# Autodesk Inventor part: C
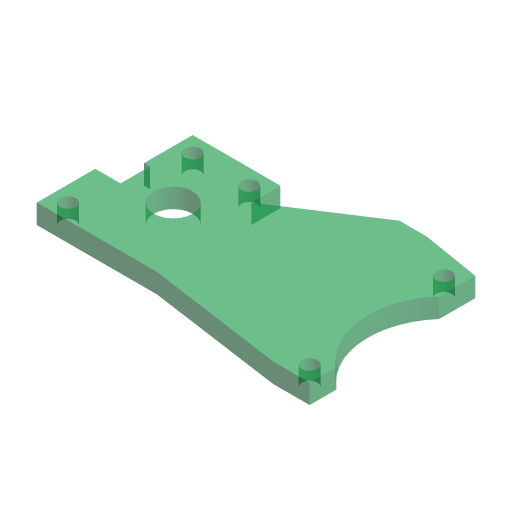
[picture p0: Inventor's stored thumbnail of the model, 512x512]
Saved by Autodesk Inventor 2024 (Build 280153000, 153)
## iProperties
Company: ATC
Shininess: 20.0
Angle Display Precision: 2
Document Length Units: 11269
Document Angle Units: 11279
Document Time Units: 11290
Document Mass Units: 11283
Document Length Units Precision: 3
Document Angle Units Precision: 2
Created: 2023-03
Part Number: C
Material: Kurs-AJ
Document SubType Name: Modelowanie
Designer: Andrzej Jaskulski
Density: 1 g/cm^3
Appearance: Przezroczyste - zielone 1
Checked By: A.J.
Engr Approved By: Andrzej Jaskulski
Mfg Approved By: Andrzej Jaskulski
Authority: A.J.
Density: 0.0
Volumn: 0.0
Area: 0.0
PropertySet Name: Model Information
Control State: 0
Master: False
Checked Out: False
Title: A.J.: Kurs R2024-MEP
Author: Andrzej Jaskulski
Revision Number: 1/24
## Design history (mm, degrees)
node "Bryła1"
node "Początek"
  node "Płaszczyzna YZ"
  node "Płaszczyzna XZ"
  node "Płaszczyzna XY"
  node "Oś X"
  node "Oś Y"
  node "Oś Z"
sketch "Szkic1"
  geometry: L1 (60, 60)-(60, 90); L2 (60, 90)-(73, 90) reference; L3 (73, 90)-(73, 105) reference; L4 (73, 105)-(70, 105) reference; L5 (70, 105)-(70, 130) reference; L6 (70, 130)-(115, 130) reference; L7 (115, 130)-(115, 115); L8 (115, 115)-(161.127, 144.955); L9 (161.127, 144.955)-(175, 144.955); L10 (175, 144.955)-(205, 139.955); L11 (205, 139.955)-(205, 121.458); L12 (60, 60)-(121.629, 60) reference; L13 (121.629, 60)-(191.251, 50) reference; L14 (191.251, 50)-(210, 50) reference; L15 (210, 50)-(210, 63.775) reference; L16 (95, 95)-(235, 95); C1 r 10 at (95, 95); C2 r 4 at (68, 68); C3 r 4 at (78, 122); C4 r 4 at (197, 131.955); C5 r 4 at (202, 58); C6 r 4 at (107, 122); A1 r 40 centre (235, 95) between (205, 121.458) and (210, 63.775)
  constraints: 32 end point, 7 centre point, 5 horizontal, 4 vertical, 2 point on circle, 1 coincident, 1 horizontal alignment, 1 perpendicular, 1 other
  dimensions: "d0" = 20 diameter of C1; "d5" = 10 distance between parallel lines of L5 L1; "d6" = 8 diameter of C3; "d7" = 8 diameter of C6 (= d6); "d8" = 8 diameter of C2 (= d6); "d9" = 8 diameter of C4 (= d6); "d10" = 8 diameter of C5 (= d6); "d11" = 8 distance from line of L6 C3.centre; "d12" = 8 distance from line of C3.centre L5 (= d11); "d13" = 8 distance from line of C6.centre L7 (= d11); "d14" = 8 distance from line of C2.centre L12 (= d11); "d15" = 8 distance from line of C2.centre L1 (= d11); "d16" = 8 distance from line of C4.centre L11 (derived); "d17" = 8 horizontal distance of C4.centre L10.end (= d11); "d18" = 8 distance from line of C5.centre L14 (= d11); "d19" = 8 distance from line of L15 C5.centre (= d11); "d20" = 35 distance from line of L12 L16.start; "d21" = 35 distance from line of L1 L16.start (= d20); "d22" = 40 radius of A1; "d25" = 140 distance of L16.start L16.end; "d26" = 135 distance between parallel lines of L11 L5; "d27" = 30 distance from line of L9.end L11; "d28" = 13 distance from line of L9 C4.centre; "d29" = 5 vertical distance of L10.end L9.end; "d30" = 90 horizontal distance of C4.centre C6.centre; "d32" = 60 distance from line of L9.end L7; "d33" = 15 distance of L6.end L7.end; "d34" = 57 deg angle of L7 L8; "d35" = 55 distance of L7.end L8.end
extrude "Wyciągnięcie proste1" new body sketch "Szkic1" distance "d1" = 10; taper "d2" = 0 deg
node "Korpusy bryłowe"
node "Korpusy powierzchniowe"
node "Punkt środkowy"
